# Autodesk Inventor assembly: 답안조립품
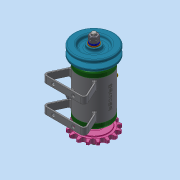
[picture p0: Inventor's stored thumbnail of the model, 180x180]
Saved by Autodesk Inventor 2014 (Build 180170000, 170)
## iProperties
Created: 2021-12
Part Number: 답안조립품
Document SubType Name: Assembly
Designer: dg
Author: dg
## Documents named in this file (16)
- C:\Users\dg\Desktop\711206V1021\답안조립품.iam
- C:\Users\dg\Desktop\711206V1021\V벨트풀리.ipt
- C:\Users\dg\Desktop\711206V1021\너트 M8.ipt
- C:\Users\dg\Desktop\711206V1021\니플 M6 x 0.75.ipt
- C:\Users\dg\Desktop\711206V1021\베어링 6002.ipt
- C:\Users\dg\Desktop\711206V1021\본체.ipt
- C:\Users\dg\Desktop\711206V1021\볼트 M4 x 12.ipt
- C:\Users\dg\Desktop\711206V1021\볼트 M6 x 8.ipt
- C:\Users\dg\Desktop\711206V1021\스프로킷.ipt
- C:\Users\dg\Desktop\711206V1021\스프링와셔 8.ipt
- C:\Users\dg\Desktop\711206V1021\오일 실 15 x 25 x 7.ipt
- C:\Users\dg\Desktop\711206V1021\와셔 6 x 11.5.ipt
- C:\Users\dg\Desktop\711206V1021\와셔 8 x 17.ipt
- C:\Users\dg\Desktop\711206V1021\축.ipt
- C:\Users\dg\Desktop\711206V1021\커버.ipt
- C:\Users\dg\Desktop\711206V1021\키 3 x 3.ipt
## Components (11 placed, 3 different names)
1. V벨트풀리:1
2. KS B 2023 6002 - 15 x 32 x 9:1
3. KS B 2023 6002 - 15 x 32 x 9:2
4. ISO 4762 M4 x 12:1
5. ISO 4762 M4 x 12:2
6. ISO 4762 M4 x 12:3
7. ISO 4762 M4 x 12:4
8. ISO 4762 M4 x 12:5
9. ISO 4762 M4 x 12:6
10. ISO 4762 M4 x 12:7
11. ISO 4762 M4 x 12:8
